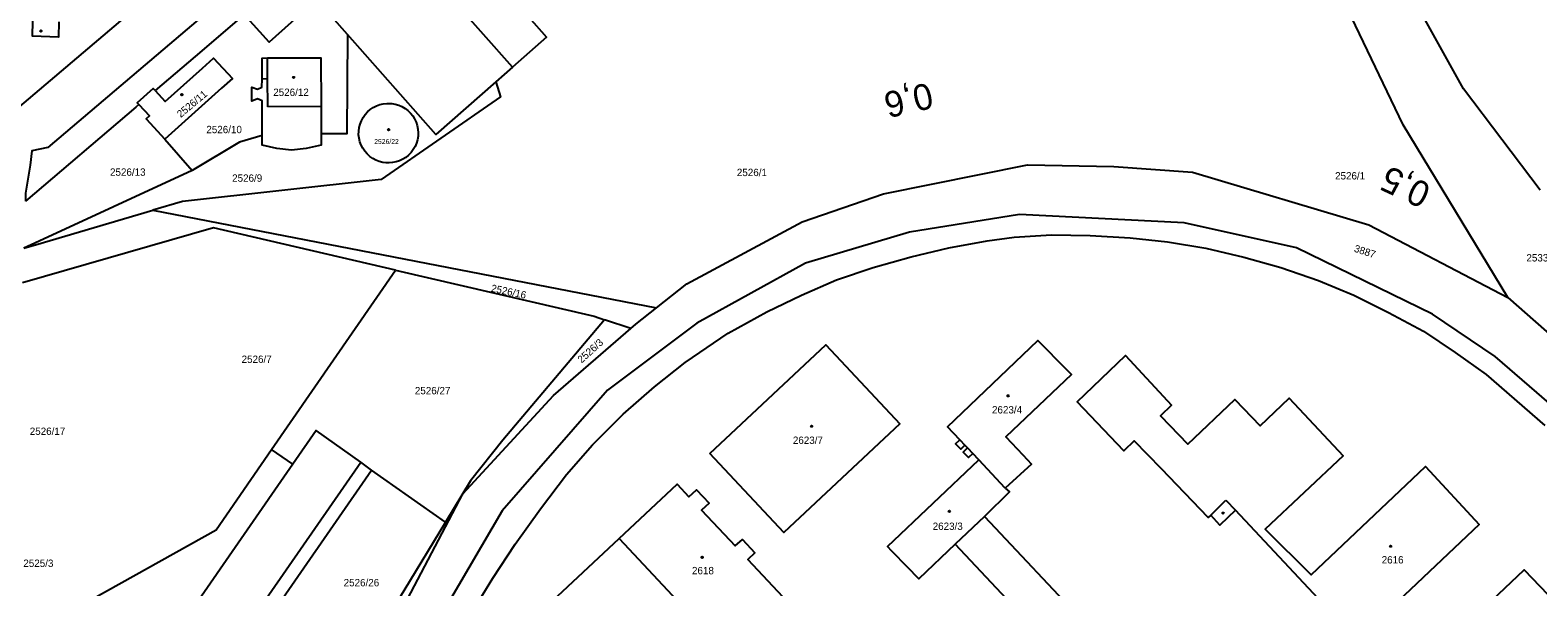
# Model space of a CAD drawing. Extents: x -527335 to -526256, y -1079142 to -1077809.
# Drawn here: x -527153.1 to -526804.7, y -1078442 to -1078313.2 of the extents above; entities that cross this region are included whole.
import ezdxf

# ---------------------------------------------------------------- set-up
doc = ezdxf.new("R2010")
doc.units = 0
for name, color, linetype in [('Vrstva 1', 7, 'Continuous'), ('Vrstva 2', 7, 'Continuous'), ('Vrstva 4', 7, 'Continuous'), ('Vrstva 5', 7, 'Continuous'), ('Vrstva 54', 7, 'Continuous'), ('Vrstva 7', 7, 'Continuous')]:
    doc.layers.add(name, color=color, linetype=linetype)

msp = doc.modelspace()

# ---------------------------------------------------------------- linework, layer by layer
at = {"layer": 'Vrstva 1'}
for p, q in [((-527079.8, -1078314.2), (-527092.36, -1078299.98)), ((-527041.68, -1078321.81), (-527045.51, -1078325.18)), ((-527122.01, -1078338.44), (-527115.65, -1078345.65)), ((-527124.8, -1078354.88), (-527008.42, -1078377.49)), ((-527097.36, -1078410.28), (-527068.7, -1078368.72)), ((-527014.31, -1078382.24), (-527020.38, -1078380.22)), ((-527092.4, -1078413.63), (-527097.36, -1078410.28)), ((-527074.28, -1078415.06), (-527076.74, -1078413.16)), ((-526927.79, -1078419.18), (-526933.9, -1078412.6)), ((-527057.14, -1078427.02), (-527074.28, -1078415.06)), ((-526932.6, -1078425.71), (-526939.37, -1078432.13)), ((-527017.02, -1078430.86), (-526997.96, -1078451.19)), ((-526904.09, -1078469.66), (-526939.37, -1078432.13))]:
    msp.add_line(p, q, dxfattribs=at)
for points in [[(-527078.01, -1078279.88), (-527149.04, -1078340.4), (-527152.71, -1078341.14), (-527153.16, -1078344.42), (-527154.22, -1078350.96), (-527154.21, -1078352.81)], [(-526811.67, -1078375.09), (-526835.85, -1078335.15), (-526859.72, -1078285.25)], [(-526804.2, -1078350.27), (-526821.9, -1078326.75), (-526841.53, -1078291.28), (-526842.74, -1078286.62)], [(-527157.99, -1078333.04), (-527157.02, -1078332.22), (-527108.84, -1078291.17)], [(-527041.68, -1078321.81), (-527061.79, -1078299.03), (-527066.22, -1078294.01)], [(-527093.17, -1078300.67), (-527087.7, -1078306.87), (-527097.86, -1078315.97), (-527103.65, -1078309.62)], [(-527103.65, -1078309.62), (-527113.42, -1078317.97), (-527124.23, -1078327.2)], [(-527037.9, -1078310.24), (-527033.83, -1078314.82), (-527041.68, -1078321.81)], [(-527146.49, -1078311.32), (-527146.56, -1078314.81), (-527152.61, -1078314.62), (-527152.53, -1078311.13)], [(-527079.8, -1078314.2), (-527079.96, -1078337.22), (-527085.89, -1078337.2)], [(-527045.51, -1078325.18), (-527059.35, -1078337.37), (-527079.8, -1078314.2)], [(-527124.23, -1078327.2), (-527121.9, -1078329.73), (-527113.33, -1078321.98), (-527110.74, -1078319.66), (-527106.36, -1078324.4), (-527108.94, -1078326.67), (-527122.01, -1078338.44)], [(-527099.54, -1078337.61), (-527099.52, -1078329.56), (-527100.62, -1078329.07), (-527101.88, -1078329.62), (-527101.91, -1078326.41), (-527100.61, -1078326.9), (-527099.56, -1078326.39), (-527099.48, -1078324.53), (-527099.52, -1078319.67), (-527098.29, -1078319.65), (-527085.93, -1078319.65), (-527085.9, -1078330.84), (-527085.89, -1078337.2)], [(-527124.23, -1078327.2), (-527124.71, -1078326.68), (-527128.43, -1078330.04), (-527128.03, -1078330.45)], [(-527045.51, -1078325.18), (-527044.42, -1078328.61), (-527072.01, -1078347.8), (-527117.91, -1078352.84), (-527124.8, -1078354.88)], [(-527128.03, -1078330.45), (-527128.68, -1078331), (-527154.21, -1078352.81)], [(-527128.03, -1078330.45), (-527125.55, -1078333.03), (-527126.31, -1078333.71), (-527122.01, -1078338.44)], [(-527063.47, -1078337.76), (-527063.61, -1078338.58), (-527063.84, -1078339.38), (-527064.17, -1078340.14), (-527064.59, -1078340.85), (-527065.09, -1078341.52), (-527065.66, -1078342.11), (-527066.31, -1078342.64), (-527067.01, -1078343.08), (-527067.76, -1078343.44), (-527068.55, -1078343.7), (-527069.36, -1078343.86), (-527070.19, -1078343.93), (-527070.82, -1078343.91), (-527071.64, -1078343.8), (-527072.45, -1078343.59), (-527073.22, -1078343.29), (-527073.95, -1078342.9), (-527074.63, -1078342.42), (-527075.24, -1078341.86), (-527075.79, -1078341.24), (-527076.25, -1078340.55), (-527076.63, -1078339.81), (-527076.92, -1078339.03), (-527077.11, -1078338.23), (-527077.21, -1078337.4), (-527077.2, -1078336.57), (-527077.09, -1078335.75), (-527076.89, -1078334.94), (-527076.59, -1078334.17), (-527076.2, -1078333.44), (-527075.72, -1078332.76), (-527075.17, -1078332.14), (-527074.55, -1078331.59), (-527073.86, -1078331.12), (-527073.12, -1078330.74), (-527072.34, -1078330.45), (-527071.54, -1078330.25), (-527070.71, -1078330.16), (-527070.4, -1078330.15), (-527069.57, -1078330.19), (-527068.76, -1078330.33), (-527067.96, -1078330.56), (-527067.2, -1078330.89), (-527066.48, -1078331.31), (-527065.82, -1078331.82), (-527065.23, -1078332.4), (-527064.71, -1078333.04), (-527064.27, -1078333.75), (-527063.92, -1078334.5), (-527063.66, -1078335.29), (-527063.5, -1078336.1), (-527063.43, -1078336.93), (-527063.47, -1078337.76)], [(-527099.54, -1078337.61), (-527104.73, -1078339.12), (-527115.65, -1078345.65)], [(-527085.89, -1078337.2), (-527085.89, -1078339.79), (-527089.34, -1078340.6), (-527092.71, -1078341), (-527096.09, -1078340.63), (-527099.54, -1078339.83), (-527099.54, -1078337.61)], [(-527008.42, -1078377.49), (-527001.38, -1078371.92), (-526974.73, -1078357.59), (-526955.89, -1078351.06), (-526922.67, -1078344.37), (-526902.66, -1078344.75), (-526884.52, -1078346.04), (-526843.79, -1078358.29), (-526811.67, -1078375.09)], [(-527115.65, -1078345.65), (-527152.02, -1078362.49), (-527154.6, -1078363.69)], [(-527154.6, -1078363.69), (-527151.91, -1078362.89), (-527124.8, -1078354.88)], [(-527068.7, -1078368.72), (-527110.78, -1078358.92), (-527154.86, -1078371.64)], [(-526758.4, -1078472.62), (-526766.27, -1078446.58), (-526780.95, -1078423.56), (-526794.44, -1078407.43), (-526800.43, -1078400.96), (-526814.56, -1078388.75), (-526829.06, -1078378.91), (-526860.51, -1078363.6), (-526886.41, -1078357.78), (-526924.51, -1078355.89), (-526949.93, -1078359.99), (-526973.92, -1078367.12), (-526999.06, -1078381.03), (-527019.7, -1078396.51), (-527044.07, -1078424.46), (-527066.65, -1078463.1), (-527068.91, -1078470.58)], [(-527068.7, -1078368.72), (-527022.78, -1078379.42), (-527020.38, -1078380.22)], [(-526811.67, -1078375.09), (-526792.46, -1078391.93), (-526770.17, -1078411.49)], [(-527014.31, -1078382.24), (-527013.19, -1078381.27), (-527008.42, -1078377.49)], [(-527073.97, -1078460.17), (-527053.17, -1078420.48), (-527032.18, -1078397.77), (-527014.31, -1078382.24)], [(-527020.38, -1078380.22), (-527043.88, -1078408.12), (-527051.36, -1078417.47), (-527057.14, -1078427.02)], [(-526996.03, -1078411.18), (-526969.26, -1078386.03), (-526952.12, -1078404.3), (-526978.92, -1078429.44), (-526996.03, -1078411.18)], [(-526933.9, -1078412.6), (-526935.3, -1078411.13), (-526936.3, -1078412.09), (-526937.48, -1078410.83), (-526936.51, -1078409.89), (-526937.1, -1078409.24), (-526938.08, -1078410.2), (-526939.29, -1078408.96), (-526938.32, -1078407.98), (-526941.1, -1078405.03), (-526920.28, -1078385.05), (-526913.63, -1078391.73), (-526912.45, -1078392.91), (-526927.69, -1078407.3), (-526923.75, -1078411.5), (-526921.74, -1078413.64), (-526927.79, -1078419.18)], [(-526840.79, -1078460.33), (-526841.89, -1078459.21), (-526874.61, -1078424.3), (-526878.19, -1078427.72), (-526880.3, -1078425.42), (-526880.87, -1078425.99), (-526891.66, -1078414.75), (-526897.96, -1078408.2), (-526900.4, -1078410.54), (-526911.2, -1078399.25), (-526900, -1078388.5), (-526889.36, -1078399.98), (-526891.93, -1078402.44), (-526885.63, -1078409.03), (-526874.72, -1078398.65), (-526868.88, -1078404.78), (-526862.16, -1078398.39), (-526849.69, -1078411.69), (-526867.72, -1078428.67), (-526857.08, -1078439.26), (-526830.69, -1078414.21), (-526818.25, -1078427.57), (-526844.26, -1078452.22), (-526838.85, -1078458.45)], [(-527076.74, -1078413.16), (-527087.02, -1078405.85), (-527092.4, -1078413.63)], [(-527141.86, -1078446.59), (-527110.16, -1078428.84), (-527097.36, -1078410.28)], [(-527092.4, -1078413.63), (-527138.83, -1078480.75), (-527128.47, -1078487.92), (-527076.74, -1078413.16)], [(-526939.37, -1078432.13), (-526947.78, -1078440.15), (-526950.36, -1078437.48), (-526953.96, -1078433.75), (-526954.97, -1078432.7), (-526933.9, -1078412.6)], [(-527079.86, -1078464.22), (-527080.96, -1078466.02), (-527100.14, -1078452.45), (-527074.28, -1078415.06)], [(-527017.02, -1078430.86), (-527003.64, -1078418.3), (-527000.89, -1078421.23), (-526999.14, -1078419.57), (-526996.24, -1078422.65), (-526998, -1078424.3), (-526990.24, -1078432.57), (-526988.5, -1078431.05), (-526985.62, -1078434.17), (-526987.27, -1078435.73), (-526979.26, -1078444.26), (-526992.65, -1078456.85), (-526997.96, -1078451.19)], [(-526927.79, -1078419.18), (-526926.8, -1078420.07), (-526932.6, -1078425.71)], [(-527057.14, -1078427.02), (-527066.8, -1078442.97), (-527076.81, -1078459.26)], [(-526932.6, -1078425.71), (-526909.39, -1078450.45), (-526905.62, -1078446.98), (-526893.64, -1078459.85), (-526895.29, -1078461.46), (-526897.29, -1078463.32)], [(-527025.9, -1078461.78), (-527037.31, -1078449.81), (-527037.19, -1078449.7), (-527017.02, -1078430.86)], [(-526838.85, -1078458.45), (-526834.26, -1078463.18), (-526807.84, -1078438.11), (-526795.26, -1078451.29), (-526823.96, -1078478.68), (-526825.34, -1078477.23)]]:
    msp.add_lwpolyline(points, dxfattribs=at)
at = {"layer": 'Vrstva 4'}
for p, q in [((-527098.24, -1078324.47), (-527098.29, -1078319.65)), ((-527098.24, -1078324.47), (-527099.48, -1078324.53)), ((-527098.18, -1078330.92), (-527098.24, -1078324.47)), ((-527085.9, -1078330.84), (-527098.18, -1078330.92)), ((-526940.81, -1078363.6), (-526932, -1078361.92)), ((-526932, -1078361.92), (-526925.74, -1078361.14)), ((-526925.74, -1078361.14), (-526917.12, -1078360.59)), ((-526917.12, -1078360.59), (-526908.16, -1078360.72)), ((-526908.16, -1078360.72), (-526898.95, -1078361.28)), ((-526898.95, -1078361.28), (-526890.27, -1078362.16)), ((-526890.27, -1078362.16), (-526881.43, -1078363.64)), ((-526958.31, -1078368.1), (-526949.55, -1078365.66)), ((-526949.55, -1078365.66), (-526940.81, -1078363.6)), ((-526881.43, -1078363.64), (-526872.65, -1078365.75)), ((-526872.65, -1078365.75), (-526864.1, -1078368.1)), ((-526966.8, -1078370.96), (-526958.31, -1078368.1)), ((-526864.1, -1078368.1), (-526855.41, -1078371.13)), ((-526974.87, -1078374.53), (-526966.8, -1078370.96)), ((-526855.41, -1078371.13), (-526847.27, -1078374.54)), ((-526982.92, -1078378.41), (-526974.87, -1078374.53)), ((-526847.27, -1078374.54), (-526839.2, -1078378.52)), ((-526991.83, -1078383.32), (-526982.92, -1078378.41)), ((-526839.2, -1078378.52), (-526831.16, -1078382.86)), ((-527001.73, -1078390.14), (-526991.83, -1078383.32)), ((-526831.16, -1078382.86), (-526823.85, -1078387.76)), ((-527008.85, -1078395.75), (-527001.73, -1078390.14)), ((-526823.85, -1078387.76), (-526816.66, -1078392.88)), ((-526816.66, -1078392.88), (-526803.07, -1078404.72)), ((-527016.12, -1078402.05), (-527008.85, -1078395.75)), ((-527023.2, -1078409.18), (-527016.12, -1078402.05)), ((-527029.21, -1078416.04), (-527023.2, -1078409.18)), ((-526938.32, -1078407.98), (-526937.1, -1078409.24)), ((-526936.51, -1078409.89), (-526935.3, -1078411.13)), ((-527035.2, -1078423.96), (-527029.21, -1078416.04)), ((-527041.08, -1078432.15), (-527035.2, -1078423.96)), ((-526880.3, -1078425.42), (-526876.81, -1078421.96)), ((-526876.81, -1078421.96), (-526874.61, -1078424.3)), ((-527046.19, -1078440.05), (-527041.08, -1078432.15)), ((-527051.06, -1078447.97), (-527046.19, -1078440.05))]:
    msp.add_line(p, q, dxfattribs=at)
at = {"layer": 'Vrstva 5'}
for centre in [(-527150.64, -1078313.4), (-527092.22, -1078324.15), (-527118.08, -1078328.15), (-527070.28, -1078336.23), (-526927.13, -1078397.82), (-526972.55, -1078404.86), (-526940.69, -1078424.54), (-526877.44, -1078424.96), (-526997.83, -1078435.21), (-526838.73, -1078432.62)]:
    msp.add_circle(centre, 0.175, dxfattribs=at)
at = {"layer": 'Vrstva 54'}
for points in [[(-527073.97, -1078460.17), (-527053.17, -1078420.48), (-527032.18, -1078397.77), (-527014.31, -1078382.24), (-527013.19, -1078381.27), (-527008.42, -1078377.49), (-527001.38, -1078371.92), (-526974.73, -1078357.59), (-526955.89, -1078351.06), (-526922.67, -1078344.37), (-526902.66, -1078344.75), (-526884.52, -1078346.04), (-526843.79, -1078358.29), (-526811.67, -1078375.09), (-526792.46, -1078391.93), (-526770.17, -1078411.49), (-526749.3, -1078465.23)], [(-526766.27, -1078446.58), (-526780.95, -1078423.56), (-526794.44, -1078407.43), (-526800.43, -1078400.96), (-526814.56, -1078388.75), (-526829.06, -1078378.91), (-526829.06, -1078378.91), (-526860.51, -1078363.6), (-526886.41, -1078357.78), (-526924.51, -1078355.89), (-526949.93, -1078359.99), (-526973.92, -1078367.12), (-526999.06, -1078381.03), (-527019.7, -1078396.51), (-527044.07, -1078424.46), (-527066.65, -1078463.1)]]:
    msp.add_lwpolyline(points, dxfattribs=at)

# ---------------------------------------------------------------- texts
at = {"layer": 'Vrstva 2'}
for s, rotation, p in [('2526/11', 40, (-527118.33, -1078333.56)), ('3887', 342, (-526847.34, -1078364.43)), ('2526/16', 348, (-527046.73, -1078373.68)), ('2526/3', 42, (-527025.69, -1078390.36))]:
    msp.add_text(s, height=1.7, rotation=rotation, dxfattribs=at).set_placement(p)
for s, height, p in [('2526/12', 1.7, (-527096.95, -1078328.43)), ('2526/10', 1.7, (-527112.41, -1078337.05)), ('2526/22', 1.14, (-527073.62, -1078339.55)), ('2526/13', 1.7, (-527134.67, -1078346.9)), ('2526/1', 1.7, (-526989.81, -1078346.98)), ('2526/9', 1.7, (-527106.45, -1078348.29)), ('2526/1', 1.7, (-526851.57, -1078347.76)), ('2533/22', 1.7, (-526807.35, -1078366.73)), ('2526/7', 1.7, (-527104.26, -1078390.21)), ('2526/27', 1.7, (-527064.22, -1078397.47)), ('2623/4', 1.7, (-526930.85, -1078401.9)), ('2526/17', 1.7, (-527153.22, -1078406.87)), ('2623/7', 1.7, (-526976.87, -1078408.95)), ('2623/3', 1.7, (-526944.56, -1078428.85)), ('2525/3', 1.7, (-527154.7, -1078437.41)), ('2616', 1.7, (-526840.8, -1078436.62)), ('2618', 1.7, (-527000.18, -1078439.11)), ('2526/26', 1.7, (-527080.68, -1078441.9))]:
    msp.add_text(s, height=height, dxfattribs=at).set_placement(p)
at = {"layer": 'Vrstva 7'}
for s, rotation, p in [('0,6', 193.0034, (-526945.35, -1078325.26)), ('0,5', 155.0475, (-526829.02, -1078349.15))]:
    msp.add_text(s, height=6, rotation=rotation, dxfattribs=at).set_placement(p)

doc.saveas('drawing.dxf')
